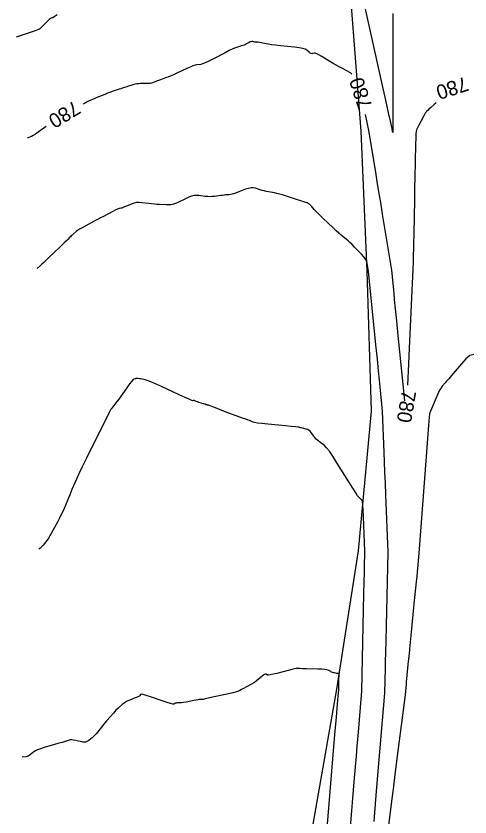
# Model space of a CAD drawing. Extents: x -26 to 1809989, y -25 to 828749.
# Drawn here: x 1809680.4 to 1809837.5, y 827618.3 to 827895.2 of the extents above; entities that cross this region are included whole.
import ezdxf

# ---------------------------------------------------------------- set-up
doc = ezdxf.new("R2010")
doc.units = 0
for name, color, linetype in [('DESIGN - CONTOURS - Index with Text', 7, 'Continuous'), ('DESIGN - CONTOURS - Intermediate with optional Text', 7, 'Continuous'), ('DESIGN - ROW - Slope Lines', 7, 'Continuous')]:
    doc.layers.add(name, color=color, linetype=linetype)

msp = doc.modelspace()

# ---------------------------------------------------------------- linework, layer by layer
at = {"layer": 'DESIGN - CONTOURS - Index with Text'}
for points in [[(1809796.65, 827875.18), (1809796.22, 827875.54), (1809793.34, 827877.05), (1809792.27, 827877.62), (1809791.19, 827878.22), (1809790.12, 827878.85), (1809789.06, 827879.49), (1809786.22, 827881.25), (1809785.26, 827881.81), (1809784.5, 827882.2), (1809783.96, 827882.4), (1809783.63, 827882.42), (1809783.01, 827882.24), (1809782.77, 827882.21), (1809782.5, 827882.28), (1809782.21, 827882.44), (1809781.89, 827882.69), (1809781.01, 827883.47), (1809780.5, 827883.76), (1809779.62, 827884.01), (1809778.36, 827884.24), (1809776.74, 827884.44), (1809771.92, 827884.94), (1809770.26, 827885.12), (1809768.88, 827885.29), (1809767.79, 827885.45), (1809767, 827885.59), (1809765.25, 827885.96), (1809764.67, 827886.08), (1809764.25, 827886.16), (1809763.98, 827886.19), (1809763.86, 827886.19), (1809763.75, 827886.14), (1809763.68, 827886.13), (1809763.55, 827886.14), (1809763.35, 827886.16), (1809763.09, 827886.21), (1809762.32, 827886.37), (1809762.03, 827886.39), (1809761.73, 827886.36), (1809761.41, 827886.26), (1809761.08, 827886.09), (1809760.2, 827885.57), (1809759.84, 827885.38), (1809759.43, 827885.2), (1809758.97, 827885.04), (1809758.46, 827884.88), (1809757.03, 827884.48), (1809756.36, 827884.25), (1809755.43, 827883.85), (1809754.24, 827883.27), (1809752.78, 827882.52), (1809748.55, 827880.31), (1809747.1, 827879.57), (1809745.92, 827879.03), (1809745.01, 827878.68), (1809744.37, 827878.52), (1809743.04, 827878.36), (1809742.44, 827878.23), (1809741.65, 827877.97), (1809740.67, 827877.58), (1809739.49, 827877.05), (1809736.08, 827875.47), (1809734.88, 827874.92), (1809733.83, 827874.46), (1809732.93, 827874.09), (1809732.18, 827873.81), (1809730.39, 827873.19), (1809729.77, 827872.97), (1809729.23, 827872.77), (1809728.8, 827872.61), (1809728.45, 827872.47), (1809727.65, 827872.14), (1809727.29, 827872.03), (1809726.82, 827871.95), (1809726.24, 827871.9), (1809725.55, 827871.88), (1809723.54, 827871.86), (1809722.83, 827871.84), (1809722.21, 827871.79), (1809721.68, 827871.7), (1809721.23, 827871.58), (1809720.15, 827871.21), (1809719.75, 827871.08), (1809719.39, 827870.96), (1809719.05, 827870.85), (1809718.74, 827870.75), (1809717.95, 827870.5), (1809717.61, 827870.39), (1809717.19, 827870.25), (1809716.69, 827870.09), (1809716.09, 827869.9), (1809714.41, 827869.35), (1809713.73, 827869.12), (1809712.95, 827868.84), (1809712.09, 827868.52), (1809711.13, 827868.14), (1809708.45, 827867.08), (1809707.43, 827866.65), (1809706.37, 827866.17), (1809705.28, 827865.63), (1809704.14, 827865.04), (1809703.7, 827864.8)], [(1809825.76, 827865.24), (1809824.96, 827864.52), (1809823.98, 827863.62), (1809823.32, 827863.01), (1809822.98, 827862.7), (1809822.51, 827862.25), (1809822.3, 827862.01), (1809822.05, 827861.64), (1809821.75, 827861.14), (1809821.4, 827860.51), (1809819.66, 827857.24), (1809819.04, 827855.93), (1809818.92, 827855.4), (1809818.82, 827854.39), (1809818.74, 827852.89), (1809818.68, 827850.89), (1809818.56, 827844.92), (1809818.44, 827839.37), (1809818.36, 827835.8), (1809818.28, 827831.68), (1809818.03, 827820), (1809817.95, 827816.1), (1809817.84, 827811.2), (1809817.82, 827810.2), (1809817.77, 827807.76), (1809816.47, 827780.35), (1809816.22, 827775.03), (1809815.87, 827767.66), (1809815.87, 827767.65)], [(1809814.93, 827762.16), (1809812.68, 827784.77), (1809812.17, 827789.88), (1809811.75, 827794.02), (1809811.44, 827797.19), (1809811.22, 827799.39), (1809810.41, 827807.41), (1809807.26, 827826.72), (1809806.61, 827830.73), (1809806, 827834.48), (1809805.43, 827837.97), (1809804.91, 827841.2), (1809802.56, 827855.67), (1809801.33, 827861.16)], [(1809690.89, 827857.01), (1809688.16, 827855.13), (1809687.13, 827854.44), (1809686.33, 827853.92), (1809685.76, 827853.58), (1809685.41, 827853.41), (1809684.31, 827853.05)]]:
    msp.add_lwpolyline(points, dxfattribs=at)
at = {"layer": 'DESIGN - CONTOURS - Intermediate with optional Text'}
for points in [[(1809810.77, 827896.1), (1809810.77, 827893.59), (1809810.78, 827890.28), (1809810.79, 827886.17), (1809810.8, 827881.25), (1809810.85, 827856.43), (1809810.82, 827855.19), (1809810.81, 827854.99), (1809810.79, 827854.92), (1809810.76, 827854.98), (1809810.73, 827855.18), (1809810.53, 827856.4), (1809810.21, 827857.81), (1809809.96, 827858.93), (1809809.34, 827861.72), (1809808.35, 827866.16), (1809806.99, 827872.25), (1809799.8, 827904.54)], [(1809694.68, 827895.6), (1809693.66, 827894.92), (1809693.18, 827894.65), (1809692.65, 827894.47), (1809692.41, 827894.35), (1809692.08, 827894.11), (1809691.68, 827893.75), (1809691.19, 827893.28), (1809689.77, 827891.86), (1809689.3, 827891.4), (1809688.77, 827890.87), (1809688.69, 827890.8), (1809688.68, 827890.79), (1809688.55, 827890.73), (1809688.39, 827890.66), (1809688.17, 827890.57), (1809687.02, 827890.07), (1809680.44, 827887.91)], [(1809804.32, 827616.82), (1809804.46, 827618.43), (1809804.71, 827621.4), (1809805.07, 827625.73), (1809805.55, 827631.41), (1809808.04, 827661.13), (1809808.23, 827669.73), (1809808.29, 827672.03), (1809808.36, 827675.23), (1809808.45, 827679.35), (1809808.57, 827684.37), (1809809.16, 827709.91), (1809808.39, 827729.7), (1809808.24, 827733.79), (1809808.09, 827737.59), (1809807.95, 827741.09), (1809807.83, 827744.31), (1809807.28, 827758.61), (1809806.44, 827767.08), (1809806.21, 827769.35), (1809805.89, 827772.53), (1809805.48, 827776.61), (1809804.98, 827781.61), (1809802.42, 827807.03), (1809801.96, 827809.81), (1809801.77, 827810.45), (1809801.37, 827811.17), (1809800.77, 827811.98), (1809799.97, 827812.87), (1809797.56, 827815.35), (1809796.71, 827816.21), (1809795.96, 827816.94), (1809795.32, 827817.53), (1809794.79, 827817.98), (1809793.5, 827818.99), (1809792.92, 827819.47), (1809792.16, 827820.14), (1809791.2, 827821.01), (1809790.05, 827822.08), (1809786.74, 827825.19), (1809785.62, 827826.26), (1809784.72, 827827.14), (1809784.04, 827827.85), (1809783.59, 827828.37), (1809782.71, 827829.5), (1809782.36, 827829.89), (1809781.98, 827830.21), (1809781.57, 827830.46), (1809781.13, 827830.64), (1809779.91, 827831.03), (1809779.37, 827831.2), (1809778.66, 827831.43), (1809777.78, 827831.72), (1809773.71, 827833.05), (1809772.62, 827833.4), (1809771.62, 827833.68), (1809770.7, 827833.91), (1809769.87, 827834.08), (1809767.77, 827834.45), (1809767.01, 827834.6), (1809766.28, 827834.76), (1809765.6, 827834.95), (1809764.95, 827835.15), (1809763.29, 827835.71), (1809762.61, 827835.84), (1809761.81, 827835.82), (1809760.9, 827835.66), (1809759.87, 827835.33), (1809756.98, 827834.27), (1809756, 827833.92), (1809755.2, 827833.67), (1809754.59, 827833.51), (1809754.18, 827833.44), (1809753.33, 827833.39), (1809752.96, 827833.36), (1809752.47, 827833.31), (1809751.87, 827833.24), (1809751.17, 827833.15), (1809749.13, 827832.86), (1809748.36, 827832.79), (1809747.57, 827832.76), (1809746.76, 827832.79), (1809745.93, 827832.88), (1809743.71, 827833.17), (1809742.87, 827833.22), (1809742.02, 827833.13), (1809741.15, 827832.91), (1809740.28, 827832.56), (1809737.94, 827831.45), (1809737.13, 827831.08), (1809736.48, 827830.78), (1809735.97, 827830.56), (1809735.62, 827830.41), (1809734.88, 827830.13), (1809734.52, 827830.04), (1809734.01, 827829.99), (1809733.34, 827829.97), (1809732.52, 827829.98), (1809730.12, 827830.07), (1809729.21, 827830.11), (1809728.3, 827830.17), (1809727.37, 827830.26), (1809726.43, 827830.37), (1809723.92, 827830.69), (1809723.01, 827830.76), (1809722.15, 827830.72), (1809721.35, 827830.57), (1809720.6, 827830.31), (1809718.67, 827829.49), (1809718.01, 827829.21), (1809717.48, 827829), (1809717.06, 827828.86), (1809716.76, 827828.79), (1809716.14, 827828.68), (1809715.82, 827828.59), (1809715.35, 827828.39), (1809714.72, 827828.08), (1809713.93, 827827.67), (1809710.7, 827825.96), (1809709.72, 827825.44), (1809708.66, 827824.88), (1809707.52, 827824.28), (1809704.39, 827822.63), (1809703.31, 827822.05), (1809702.43, 827821.54), (1809701.75, 827821.09), (1809701.27, 827820.72), (1809700.24, 827819.82), (1809699.87, 827819.5), (1809699.54, 827819.2), (1809699.25, 827818.91), (1809698.99, 827818.65), (1809698.34, 827817.99), (1809697.98, 827817.62), (1809697.36, 827817.02), (1809696.49, 827816.19), (1809695.36, 827815.11), (1809692.03, 827811.95), (1809690.9, 827810.88), (1809690.02, 827810.04), (1809689.39, 827809.43), (1809689.01, 827809.06), (1809687.79, 827807.89)], [(1809838.85, 827778.25), (1809837.45, 827777.85), (1809836.06, 827776.67), (1809832.38, 827772.45), (1809831.13, 827771.01), (1809830.13, 827769.86), (1809829.38, 827769), (1809828.89, 827768.42), (1809827.9, 827767.25), (1809827.52, 827766.73), (1809827.1, 827766.02), (1809826.65, 827765.14), (1809826.17, 827764.07), (1809823.87, 827758.68), (1809823.5, 827757.66), (1809823.36, 827756.58), (1809823.12, 827753.76), (1809822.76, 827749.2), (1809822.29, 827742.91), (1809819.86, 827709.49), (1809819.07, 827701.53), (1809818.88, 827699.58), (1809818.35, 827694.21), (1809818.01, 827690.79), (1809817.04, 827681.02), (1809816.71, 827677.64), (1809816.43, 827674.84), (1809816.05, 827670.99), (1809815.7, 827667.39), (1809815.57, 827666.13), (1809815.47, 827665.06), (1809815.38, 827664.16), (1809815.02, 827660.55), (1809812.02, 827636.7), (1809811.43, 827631.96), (1809810.92, 827627.94), (1809810.51, 827624.65), (1809808.9, 827611.84)], [(1809796.02, 827613.47), (1809797.55, 827631.81), (1809797.88, 827635.66), (1809798.19, 827639.36), (1809798.48, 827642.91), (1809798.77, 827646.3), (1809800.07, 827661.79), (1809800.71, 827690.04), (1809800.83, 827695.49), (1809800.92, 827699.72), (1809800.99, 827702.75), (1809801.04, 827704.57), (1809801.17, 827710.22), (1809800.7, 827722.24), (1809800.59, 827724.51), (1809800.48, 827726.18), (1809800.34, 827727.25), (1809800.2, 827727.72), (1809799.79, 827728.16), (1809799.64, 827728.32), (1809799.5, 827728.47), (1809799.37, 827728.59), (1809799.25, 827728.7), (1809798.93, 827728.98), (1809798.63, 827729.38), (1809797.97, 827730.38), (1809796.96, 827731.97), (1809795.6, 827734.16), (1809791.48, 827740.78), (1809790.05, 827743.02), (1809788.85, 827744.75), (1809787.87, 827745.99), (1809787.13, 827746.73), (1809785.46, 827748.02), (1809784.86, 827748.51), (1809784.34, 827749), (1809783.88, 827749.48), (1809783.49, 827749.97), (1809782.56, 827751.27), (1809782.19, 827751.7), (1809781.78, 827752.05), (1809781.35, 827752.29), (1809780.88, 827752.44), (1809779.57, 827752.72), (1809779.14, 827752.81), (1809778.81, 827752.88), (1809778.6, 827752.94), (1809778.49, 827752.97), (1809778.34, 827753.04), (1809778.01, 827753.09), (1809777.11, 827753.19), (1809775.66, 827753.34), (1809773.64, 827753.53), (1809767.52, 827754.12), (1809765.49, 827754.33), (1809763.98, 827754.5), (1809762.98, 827754.66), (1809762.51, 827754.78), (1809761.94, 827755.08), (1809761.75, 827755.18), (1809761.61, 827755.25), (1809761.52, 827755.3), (1809761.47, 827755.32), (1809761.41, 827755.34), (1809761.23, 827755.4), (1809760.74, 827755.57), (1809759.93, 827755.86), (1809758.8, 827756.26), (1809752.82, 827758.38), (1809748.92, 827759.95), (1809748.17, 827760.25), (1809747.61, 827760.47), (1809747.23, 827760.61), (1809747.03, 827760.67), (1809746.74, 827760.74), (1809746.57, 827760.78), (1809746.28, 827760.87), (1809745.87, 827761), (1809745.33, 827761.17), (1809743.74, 827761.67), (1809743.21, 827761.84), (1809742.8, 827761.98), (1809742.52, 827762.08), (1809742.36, 827762.15), (1809742.09, 827762.29), (1809742, 827762.33), (1809741.91, 827762.35), (1809741.84, 827762.35), (1809741.77, 827762.33), (1809741.61, 827762.24), (1809741.28, 827762.35), (1809740.38, 827762.72), (1809738.92, 827763.37), (1809736.91, 827764.3), (1809730.78, 827767.12), (1809728.71, 827768.06), (1809727.06, 827768.77), (1809725.86, 827769.23), (1809725.08, 827769.46), (1809723.6, 827769.75), (1809723.11, 827769.85), (1809722.73, 827769.91), (1809722.46, 827769.94), (1809722.32, 827769.95), (1809722.08, 827769.92), (1809721.99, 827769.9), (1809721.88, 827769.88), (1809721.76, 827769.86), (1809721.62, 827769.83), (1809721.23, 827769.74), (1809720.98, 827769.53), (1809720.48, 827768.95), (1809719.76, 827768.02), (1809718.81, 827766.72), (1809715.96, 827762.79), (1809715.01, 827761.49), (1809714.32, 827760.54), (1809713.87, 827759.95), (1809713.67, 827759.71), (1809713.48, 827759.55), (1809713.4, 827759.47), (1809713.31, 827759.37), (1809713.22, 827759.23), (1809713.12, 827759.06), (1809712.63, 827758.2), (1809704.88, 827742.43), (1809703.38, 827739.36), (1809702.2, 827736.91), (1809701.34, 827735.09), (1809700.81, 827733.89), (1809699.81, 827731.53), (1809699.43, 827730.62), (1809699.04, 827729.69), (1809698.63, 827728.72), (1809698.22, 827727.72), (1809697.09, 827725.01), (1809696.64, 827723.96), (1809696.11, 827722.85), (1809695.52, 827721.68), (1809694.86, 827720.44), (1809691.62, 827714.52), (1809689.82, 827712.35), (1809689.47, 827711.93), (1809689.2, 827711.61), (1809688.99, 827711.39), (1809688.85, 827711.26), (1809688.38, 827710.89)], [(1809788.09, 827614.48), (1809790.79, 827646.8), (1809791.29, 827652.89), (1809791.66, 827657.32), (1809791.9, 827660.09), (1809791.99, 827661.19), (1809792.09, 827662.45), (1809792.18, 827666.18), (1809792.19, 827666.88), (1809792.19, 827667.38), (1809792.19, 827667.69), (1809792.17, 827667.81), (1809792.12, 827667.86), (1809792.06, 827667.88), (1809791.93, 827667.91), (1809791.72, 827667.94), (1809791.44, 827667.99), (1809790.6, 827668.12), (1809790.28, 827668.18), (1809789.96, 827668.28), (1809789.64, 827668.41), (1809789.32, 827668.57), (1809788.46, 827669.05), (1809787.99, 827669.21), (1809787.24, 827669.33), (1809786.19, 827669.42), (1809784.85, 827669.47), (1809780.9, 827669.55), (1809779.59, 827669.58), (1809778.64, 827669.61), (1809778.05, 827669.63), (1809777.81, 827669.66), (1809777.66, 827669.72), (1809777.42, 827669.69), (1809776.84, 827669.56), (1809775.9, 827669.33), (1809774.61, 827669), (1809770.7, 827667.98), (1809769.39, 827667.66), (1809768.41, 827667.46), (1809767.76, 827667.37), (1809767.43, 827667.41), (1809766.98, 827667.68), (1809766.77, 827667.71), (1809766.45, 827667.6), (1809766.05, 827667.35), (1809765.55, 827666.97), (1809762.98, 827664.86), (1809759.18, 827662.79), (1809758.44, 827662.39), (1809757.86, 827662.09), (1809757.45, 827661.88), (1809757.19, 827661.76), (1809756.71, 827661.58), (1809756.34, 827661.48), (1809755.59, 827661.29), (1809754.47, 827661.03), (1809752.97, 827660.7), (1809748.46, 827659.7), (1809746.97, 827659.37), (1809745.88, 827659.14), (1809745.18, 827658.99), (1809744.89, 827658.94), (1809744.63, 827658.94), (1809744.53, 827658.93), (1809744.44, 827658.93), (1809744.35, 827658.93), (1809744.27, 827658.92), (1809744.05, 827658.91), (1809743.86, 827658.89), (1809743.44, 827658.82), (1809742.79, 827658.71), (1809741.92, 827658.55), (1809739.28, 827658.08), (1809738.4, 827657.93), (1809737.71, 827657.82), (1809737.23, 827657.76), (1809736.95, 827657.75), (1809736.48, 827657.77), (1809736.3, 827657.77), (1809736.1, 827657.74), (1809735.89, 827657.69), (1809735.67, 827657.62), (1809735.07, 827657.38), (1809734.66, 827657.38), (1809733.9, 827657.54), (1809732.79, 827657.86), (1809731.33, 827658.35), (1809726.94, 827659.87), (1809725.5, 827660.35), (1809724.44, 827660.65), (1809723.77, 827660.77), (1809723.5, 827660.71), (1809723.28, 827660.3), (1809723.12, 827660.14), (1809722.8, 827659.95), (1809722.32, 827659.72), (1809721.69, 827659.47), (1809719.79, 827658.77), (1809719.09, 827658.48), (1809718.43, 827658.12), (1809717.81, 827657.7), (1809717.22, 827657.22), (1809715.7, 827655.86), (1809715.03, 827655.2), (1809714.15, 827654.26), (1809713.08, 827653.04), (1809711.8, 827651.53), (1809708.13, 827647.12), (1809706.81, 827645.7), (1809705.61, 827644.74), (1809704.53, 827644.24), (1809703.57, 827644.21), (1809701.17, 827644.74), (1809700.35, 827644.9), (1809699.69, 827644.98), (1809699.18, 827644.99), (1809698.82, 827644.92), (1809698.09, 827644.64), (1809697.83, 827644.54), (1809697.59, 827644.46), (1809697.38, 827644.39), (1809697.2, 827644.34), (1809696.74, 827644.22), (1809696.43, 827644.13), (1809695.82, 827643.95), (1809694.92, 827643.69), (1809693.72, 827643.34), (1809690.15, 827642.3), (1809688.92, 827641.91), (1809687.92, 827641.54), (1809687.14, 827641.17), (1809686.59, 827640.82), (1809685.41, 827639.89), (1809684.98, 827639.58), (1809684.6, 827639.36), (1809684.25, 827639.21), (1809683.94, 827639.15), (1809682.59, 827639.04)]]:
    msp.add_lwpolyline(points, dxfattribs=at)
at = {"layer": 'DESIGN - ROW - Slope Lines'}
for p, q in [((1809799.83, 827855.42), (1809796.11, 827904.07)), ((1809801.95, 827807), (1809799.83, 827855.42)), ((1809803.44, 827758.6), (1809801.95, 827807)), ((1809798.89, 827710.31), (1809803.44, 827758.6)), ((1809791.39, 827662.51), (1809798.89, 827710.31)), ((1809783.11, 827615.11), (1809791.39, 827662.51))]:
    msp.add_line(p, q, dxfattribs=at)

# ---------------------------------------------------------------- texts
at = {"layer": 'DESIGN - CONTOURS - Index with Text'}
for rotation, p in [(108.4591, (1809803.86, 827863.91)), (197.9633, (1809835.94, 827874.38)), (211.2898, (1809700.69, 827866.21)), (260.3157, (1809814, 827766.15))]:
    msp.add_text('780', height=5, rotation=rotation, dxfattribs=at).set_placement(p)

doc.saveas('drawing.dxf')
